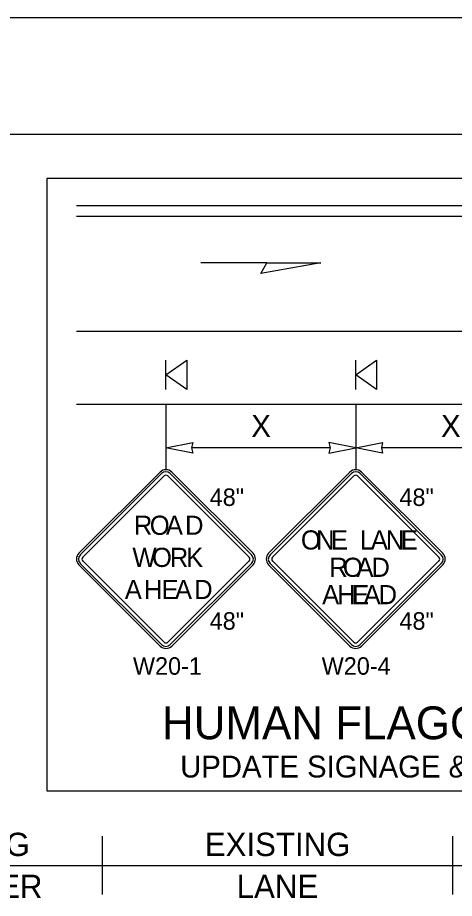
# Model space of a CAD drawing. Extents: x 99999.1 to 100095.7, y 99995 to 100010.7.
# Drawn here: x 100005 to 100006.496, y 100003.112 to 100006.132 of the extents above; entities that cross this region are included whole.
import ezdxf

# ---------------------------------------------------------------- set-up
doc = ezdxf.new("R2010")
doc.units = 0
for name, color, linetype in [('RD_ED_ShoulderPavedEdge', 7, 'Continuous'), ('RD_MK_LineDblYellowCenter', 7, 'Continuous'), ('RD_MK_LineEdgeWhite', 7, 'Continuous'), ('SH_DE_DetailHeading2Text', 7, 'Continuous'), ('TR_SN_ConstructionSigns', 7, 'Continuous'), ('TR_WZ_PortableSignMountBlk-Org', 7, 'Continuous'), ('TR_WZ_WorkZoneDetails', 7, 'Continuous'), ('TR_WZ_WorkZoneTextCurrent', 7, 'Continuous')]:
    doc.layers.add(name, color=color, linetype=linetype)

msp = doc.modelspace()

# ---------------------------------------------------------------- linework, layer by layer
at = {"layer": 'RD_ED_ShoulderPavedEdge'}
for p, q in [((100000.1076, 100005.7323), (100015.6424, 100005.7323)), ((100005.2015, 100004.8073), (100008.9925, 100004.8073))]:
    msp.add_line(p, q, dxfattribs=at)
at = {"layer": 'RD_MK_LineDblYellowCenter'}
for p, q in [((100005.2015, 100005.4886), (100008.0081, 100005.4886)), ((100005.2015, 100005.4511), (100008.0081, 100005.4511))]:
    msp.add_line(p, q, dxfattribs=at)
at = {"layer": 'RD_MK_LineEdgeWhite'}
for p, q in [((100000.1076, 100006.1323), (100015.6424, 100006.1323)), ((100005.2015, 100005.0573), (100008.9925, 100005.0573))]:
    msp.add_line(p, q, dxfattribs=at)
at = {"layer": 'TR_SN_ConstructionSigns'}
for p, q in [((100005.4882, 100004.5741), (100005.2098, 100004.2957)), ((100005.8064, 100004.2957), (100005.528, 100004.5741)), ((100006.1382, 100004.5741), (100005.8598, 100004.2957)), ((100006.4564, 100004.2957), (100006.178, 100004.5741)), ((100005.4932, 100004.5691), (100005.2147, 100004.2907)), ((100005.223, 100004.2824), (100005.5015, 100004.5608)), ((100005.5147, 100004.5608), (100005.7931, 100004.2824)), ((100005.8014, 100004.2907), (100005.523, 100004.5691)), ((100006.1432, 100004.5691), (100005.8647, 100004.2907)), ((100005.873, 100004.2824), (100006.1515, 100004.5608)), ((100006.1647, 100004.5608), (100006.4431, 100004.2824)), ((100006.4514, 100004.2907), (100006.173, 100004.5691)), ((100005.2098, 100004.2559), (100005.4882, 100003.9775)), ((100005.2147, 100004.2609), (100005.4932, 100003.9824)), ((100005.5015, 100003.9907), (100005.223, 100004.2692)), ((100005.7931, 100004.2692), (100005.5147, 100003.9907)), ((100005.523, 100003.9824), (100005.8014, 100004.2609)), ((100005.528, 100003.9775), (100005.8064, 100004.2559)), ((100005.8598, 100004.2559), (100006.1382, 100003.9775)), ((100005.8647, 100004.2609), (100006.1432, 100003.9824)), ((100006.1515, 100003.9907), (100005.873, 100004.2692)), ((100006.4431, 100004.2692), (100006.1647, 100003.9907)), ((100006.173, 100003.9824), (100006.4514, 100004.2609)), ((100006.178, 100003.9775), (100006.4564, 100004.2559))]:
    msp.add_line(p, q, dxfattribs=at)
for centre, radius, start, end in [((100005.5081, 100004.5542), 0.0281, 45, 135), ((100005.5081, 100004.5542), 0.0211, 45, 135), ((100006.1581, 100004.5542), 0.0281, 45, 135), ((100006.1581, 100004.5542), 0.0211, 45, 135), ((100005.5081, 100004.5542), 0.00938, 45, 135), ((100006.1581, 100004.5542), 0.00938, 45, 135), ((100005.2297, 100004.2758), 0.0281, 135, 225), ((100005.2297, 100004.2758), 0.0211, 135, 225), ((100005.2297, 100004.2758), 0.00938, 135, 225), ((100005.7865, 100004.2758), 0.00938, 315, 45), ((100005.7865, 100004.2758), 0.0211, 315, 45), ((100005.7865, 100004.2758), 0.0281, 315, 45), ((100005.8797, 100004.2758), 0.0281, 135, 225), ((100005.8797, 100004.2758), 0.0211, 135, 225), ((100005.8797, 100004.2758), 0.00938, 135, 225), ((100006.4365, 100004.2758), 0.00938, 315, 45), ((100006.4365, 100004.2758), 0.0211, 315, 45), ((100006.4365, 100004.2758), 0.0281, 315, 45), ((100005.5081, 100003.9974), 0.0281, 225, 315), ((100005.5081, 100003.9974), 0.0211, 225, 315), ((100005.5081, 100003.9974), 0.00938, 225, 315), ((100006.1581, 100003.9974), 0.0281, 225, 315), ((100006.1581, 100003.9974), 0.0211, 225, 315), ((100006.1581, 100003.9974), 0.00938, 225, 315)]:
    msp.add_arc(centre, radius, start, end, dxfattribs=at)
at = {"layer": 'TR_WZ_PortableSignMountBlk-Org'}
for p, q in [((100005.5081, 100004.8574), (100005.5081, 100004.9574)), ((100006.1581, 100004.8574), (100006.1581, 100004.9574))]:
    msp.add_line(p, q, dxfattribs=at)
for points in [[(100005.5081, 100004.9073), (100005.5799, 100004.9574), (100005.5799, 100004.8574)], [(100006.1581, 100004.9073), (100006.2299, 100004.9574), (100006.2299, 100004.8574)]]:
    msp.add_lwpolyline(points, close=True, dxfattribs=at)
at = {"layer": 'TR_WZ_WorkZoneDetails'}
for p, q in [((100005.854, 100005.291), (100005.6279, 100005.291)), ((100005.5081, 100004.8073), (100005.5081, 100004.5823)), ((100006.1581, 100004.8073), (100006.1581, 100004.5823)), ((100006.0702, 100004.6573), (100005.596, 100004.6573)), ((100006.7202, 100004.6573), (100006.246, 100004.6573)), ((100005.2907, 100003.1255), (100005.2907, 100003.3255)), ((100006.4907, 100003.1255), (100006.4907, 100003.3255)), ((100004.2907, 100003.2255), (100005.2907, 100003.2255)), ((100005.2907, 100003.2255), (100006.4907, 100003.2255)), ((100006.4907, 100003.2255), (100007.6907, 100003.2255))]:
    msp.add_line(p, q, dxfattribs=at)
for points in [[(100006.0382, 100005.291), (100005.8331, 100005.2549), (100005.854, 100005.291)], [(100005.5081, 100004.6573), (100005.6002, 100004.6754), (100005.596, 100004.6573), (100005.6002, 100004.6393)], [(100006.1581, 100004.6573), (100006.0659, 100004.6754), (100006.0702, 100004.6573), (100006.0659, 100004.6393)], [(100006.1581, 100004.6573), (100006.2502, 100004.6754), (100006.246, 100004.6573), (100006.2502, 100004.6393)]]:
    msp.add_lwpolyline(points, close=True, dxfattribs=at)
at = {"layer": 'TR_WZ_WorkZoneTextCurrent'}
msp.add_lwpolyline([(100005.1015, 100005.5823), (100009.1102, 100005.5823), (100009.1102, 100003.4799), (100005.1015, 100003.4799)], close=True, dxfattribs=at)

# ---------------------------------------------------------------- texts
at = {"layer": 'SH_DE_DetailHeading2Text'}
msp.add_text('HUMAN FLAGGER SUBSTITUTION', height=0.1125, rotation=360, dxfattribs=at).set_placement((100005.4946, 100003.658))
at = {"layer": 'TR_SN_ConstructionSigns'}
for s, p in [('48"', (100005.6579, 100004.4579)), ('48"', (100006.3079, 100004.4579)), ('48"', (100005.6579, 100004.0337)), ('48"', (100006.3079, 100004.0337)), ('W20-1', (100005.3949, 100003.8792)), ('W20-4', (100006.0415, 100003.8792))]:
    msp.add_text(s, height=0.06, rotation=360, dxfattribs=at).set_placement(p)
for s, p in [('R', (100005.3982, 100004.359)), ('O', (100005.4526, 100004.359)), ('A', (100005.5078, 100004.359)), ('D', (100005.5734, 100004.359)), ('O', (100005.9704, 100004.3086)), ('N', (100006.0222, 100004.3086)), ('E', (100006.0734, 100004.3086)), ('L', (100006.1725, 100004.3086)), ('A', (100006.2099, 100004.3086)), ('N', (100006.2611, 100004.3086)), ('E', (100006.3123, 100004.3086)), ('W', (100005.3932, 100004.2488)), ('O', (100005.4602, 100004.2488)), ('R', (100005.5212, 100004.2488)), ('K', (100005.577, 100004.2488)), ('R', (100006.0675, 100004.2148)), ('O', (100006.1141, 100004.2148)), ('A', (100006.1607, 100004.2148)), ('D', (100006.2119, 100004.2148)), ('A', (100005.367, 100004.1387)), ('H', (100005.4326, 100004.1387)), ('E', (100005.493, 100004.1387)), ('A', (100005.5389, 100004.1387)), ('D', (100005.6046, 100004.1387)), ('A', (100006.0432, 100004.1211)), ('H', (100006.0944, 100004.1211)), ('E', (100006.1456, 100004.1211)), ('A', (100006.185, 100004.1211)), ('D', (100006.2362, 100004.1211))]:
    msp.add_text(s, height=0.0656, dxfattribs=at).set_placement(p)
at = {"layer": 'TR_WZ_WorkZoneDetails'}
for s, p in [('EXISTING', (100004.5424, 100003.2575)), ('EXISTING', (100005.6409, 100003.2575)), ('SHOULDER', (100004.4905, 100003.1135)), ('LANE', (100005.7503, 100003.1135))]:
    msp.add_text(s, height=0.08, rotation=360, dxfattribs=at).set_placement(p)
at = {"layer": 'TR_WZ_WorkZoneTextCurrent'}
for p in [(100005.8005, 100004.6948), (100006.4505, 100004.6948)]:
    msp.add_text('X', height=0.075, rotation=360, dxfattribs=at).set_placement(p)
msp.add_text('UPDATE SIGNAGE & USE STOP/SLOW PADDLE', height=0.075, dxfattribs=at).set_placement((100005.5568, 100003.5268))

doc.saveas('drawing.dxf')
